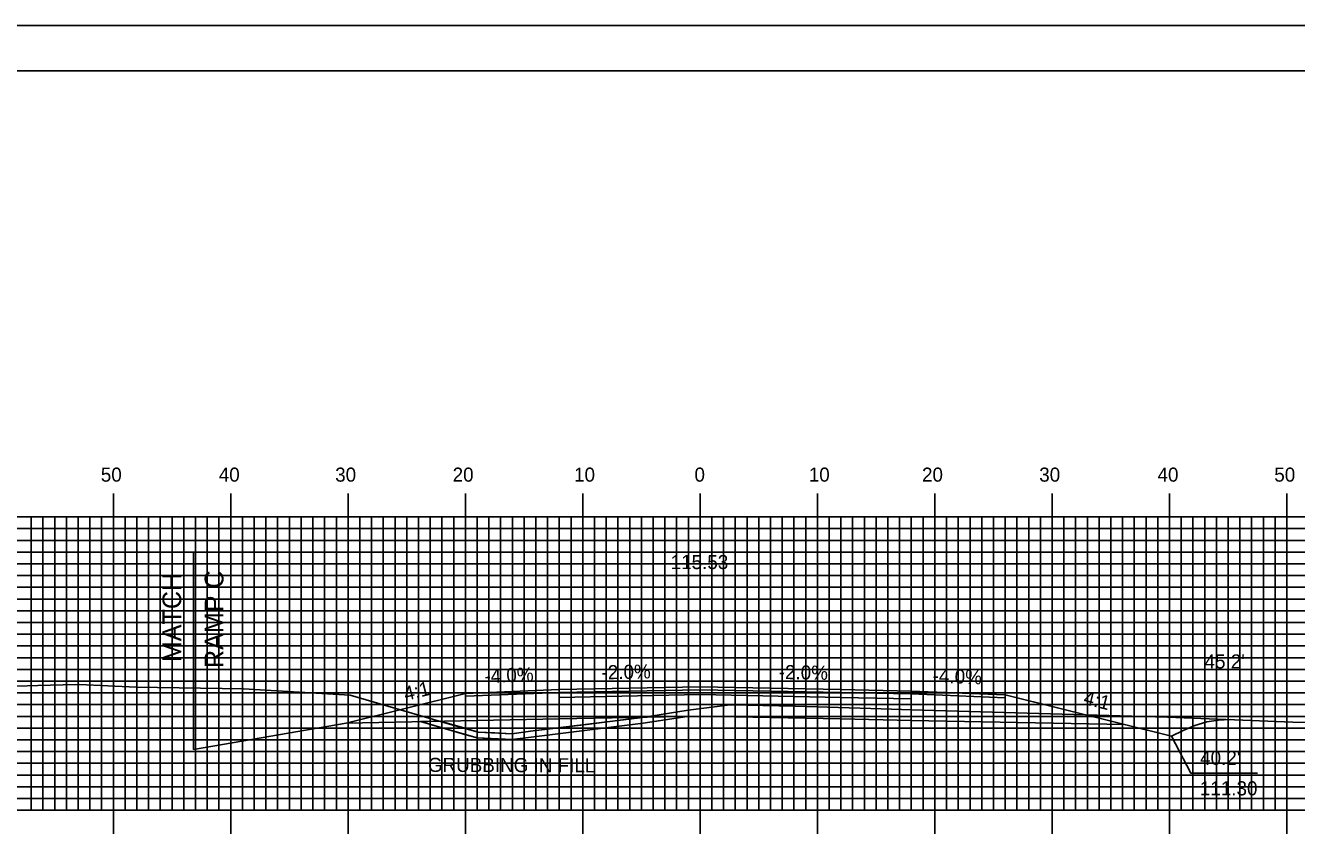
# Model space of a CAD drawing. Extents: x 1754314 to 1754654, y 442591 to 442811.
# Drawn here: x 1754422.5 to 1754530.8, y 442741.2 to 442810.5 of the extents above; entities that cross this region are included whole.
import ezdxf

# ---------------------------------------------------------------- set-up
doc = ezdxf.new("R2010")
doc.units = 0
for name, color, linetype in [('ANNOTATION', 7, 'Continuous'), ('BORDER', 7, 'Continuous'), ('D_Roadway_Centerline', 7, 'Continuous'), ('D_Roadway_Centerline_Text', 7, 'Continuous'), ('D_Roadway_Edge_Shoulder', 7, 'Continuous'), ('D_Roadway_Edge_TW', 7, 'Continuous'), ('D_Roadway_Pavement', 7, 'Continuous'), ('D_Roadway_SlopeLines', 7, 'Continuous'), ('D_Roadway_SubGrade', 7, 'Continuous'), ('D_Text_Standard', 7, 'Continuous'), ('GRUBBING IN FILL', 7, 'Continuous'), ('H_V ANNOTATION', 7, 'Continuous'), ('M_Roadway_Centerline', 7, 'Continuous'), ('MAJOR', 7, 'Continuous'), ('MINOR', 7, 'Continuous'), ('PLOT BOUNDARY', 7, 'Continuous'), ('S_Roadway_Centerline', 7, 'Continuous')]:
    doc.layers.add(name, color=color, linetype=linetype)

msp = doc.modelspace()

# ---------------------------------------------------------------- linework, layer by layer
at = {"layer": 'ANNOTATION'}
msp.add_lwpolyline([(1754527.51, 442746.82), (1754521.82, 442746.82), (1754520.18, 442749.97)], dxfattribs=at)
at = {"layer": 'BORDER'}
msp.add_lwpolyline([(1754330.4, 442596.67), (1754650.4, 442596.67), (1754650.4, 442806.67), (1754330.4, 442806.67)], close=True, dxfattribs=at)
at = {"layer": 'D_Roadway_Centerline'}
msp.add_lwpolyline([(1754436.83, 442748.85), (1754449.83, 442751.09), (1754460, 442753.63), (1754468, 442753.95), (1754480, 442754.19), (1754492, 442753.95), (1754498, 442753.83), (1754506, 442753.51), (1754516.18, 442750.97), (1754520.18, 442749.97), (1754521.17, 442750.46), (1754522.17, 442750.9), (1754523.17, 442751.2), (1754524.17, 442751.36), (1754525.17, 442751.39)], dxfattribs=at)
at = {"layer": 'D_Roadway_Edge_Shoulder'}
for points in [[(1754468, 442753.95), (1754460, 442753.63), (1754460, 442753.38), (1754468, 442753.7)], [(1754498, 442753.83), (1754506, 442753.51), (1754506, 442753.26), (1754498, 442753.58)]]:
    msp.add_lwpolyline(points, close=True, dxfattribs=at)
at = {"layer": 'D_Roadway_Edge_TW'}
for points in [[(1754468, 442753.7), (1754468, 442753.95), (1754480, 442754.19), (1754492, 442753.95), (1754492, 442753.7), (1754480, 442753.94)], [(1754492, 442753.95), (1754498, 442753.83), (1754498, 442753.58), (1754492, 442753.7)]]:
    msp.add_lwpolyline(points, close=True, dxfattribs=at)
at = {"layer": 'D_Roadway_Pavement'}
for points in [[(1754468, 442753.29), (1754468, 442753.7), (1754480, 442753.94), (1754492, 442753.7), (1754492, 442753.29), (1754480, 442753.53)], [(1754492, 442753.7), (1754498, 442753.58), (1754498, 442753.17), (1754492, 442753.29)]]:
    msp.add_lwpolyline(points, close=True, dxfattribs=at)
msp.add_lwpolyline([(1754498, 442753.58), (1754498, 442753.17)], dxfattribs=at)
msp.add_lwpolyline([(1754498, 442753.58), (1754498, 442753.17)], dxfattribs=at)
msp.add_lwpolyline([(1754498, 442753.58), (1754498, 442753.17)], dxfattribs=at)
at = {"layer": 'D_Roadway_SlopeLines'}
for p, q in [((1754460, 442753.63), (1754449.83, 442751.09)), ((1754436.83, 442748.85), (1754436.83, 442753.15)), ((1754449.83, 442751.09), (1754436.83, 442748.85))]:
    msp.add_line(p, q, dxfattribs=at)
for points in [[(1754506, 442753.51), (1754520.18, 442749.97)], [(1754520.18, 442749.97), (1754521.17, 442750.46), (1754522.17, 442750.9), (1754523.17, 442751.2), (1754524.17, 442751.36), (1754525.17, 442751.39)]]:
    msp.add_lwpolyline(points, dxfattribs=at)
at = {"layer": 'D_Roadway_SubGrade'}
msp.add_line((1754436.83, 442765.63), (1754436.83, 442748.85), dxfattribs=at)
for points in [[(1754460, 442753.38), (1754468, 442753.7), (1754468, 442753.29), (1754468, 442751.45), (1754449.83, 442751.09), (1754460, 442753.63)], [(1754468, 442751.45), (1754468, 442753.29), (1754480, 442753.53), (1754492, 442753.29), (1754492, 442751.45), (1754480, 442751.69)], [(1754498, 442753.17), (1754498, 442753.58), (1754506, 442753.26), (1754506, 442753.51), (1754516.18, 442750.97), (1754498, 442751.33)], [(1754492, 442753.29), (1754498, 442753.17), (1754498, 442751.33), (1754492, 442751.45)]]:
    msp.add_lwpolyline(points, close=True, dxfattribs=at)
at = {"layer": 'GRUBBING IN FILL'}
msp.add_lwpolyline([(1754456.18, 442751.22), (1754458.5, 442750.54), (1754461, 442749.83), (1754463.98, 442749.69), (1754465.61, 442749.9), (1754475.15, 442751.09), (1754478.9, 442751.67)], dxfattribs=at)
msp.add_lwpolyline([(1754456.18, 442751.22), (1754458.5, 442750.54), (1754461, 442749.83), (1754463.98, 442749.69), (1754465.61, 442749.9), (1754475.15, 442751.09), (1754478.9, 442751.67)], dxfattribs=at)
msp.add_lwpolyline([(1754456.18, 442751.22), (1754457.86, 442751.25), (1754459.86, 442750.68), (1754461.08, 442750.33), (1754462.52, 442750.26), (1754463.96, 442750.19), (1754464.75, 442750.29), (1754465.54, 442750.4), (1754470.31, 442750.99), (1754475.18, 442751.6), (1754478.9, 442751.67), (1754475.15, 442751.09), (1754470.38, 442750.49), (1754465.61, 442749.9), (1754463.98, 442749.69), (1754462.49, 442749.76), (1754461, 442749.83), (1754459.75, 442750.19)], close=True, dxfattribs=at)
msp.add_lwpolyline([(1754456.18, 442751.22), (1754457.86, 442751.25), (1754459.86, 442750.68), (1754461.08, 442750.33), (1754462.52, 442750.26), (1754463.96, 442750.19), (1754464.75, 442750.29), (1754465.54, 442750.4), (1754470.31, 442750.99), (1754475.18, 442751.6), (1754478.9, 442751.67), (1754475.15, 442751.09), (1754470.38, 442750.49), (1754465.61, 442749.9), (1754463.98, 442749.69), (1754462.49, 442749.76), (1754461, 442749.83), (1754459.75, 442750.19)], close=True, dxfattribs=at)
at = {"layer": 'MAJOR'}
for p, q in [((1754430, 442770.67), (1754430, 442768.67)), ((1754440, 442770.67), (1754440, 442768.67)), ((1754450, 442770.67), (1754450, 442768.67)), ((1754460, 442770.67), (1754460, 442768.67)), ((1754470, 442770.67), (1754470, 442768.67)), ((1754480, 442770.67), (1754480, 442768.67)), ((1754490, 442770.67), (1754490, 442768.67)), ((1754500, 442770.67), (1754500, 442768.67)), ((1754510, 442770.67), (1754510, 442768.67)), ((1754520, 442770.67), (1754520, 442768.67)), ((1754530, 442770.67), (1754530, 442768.67)), ((1754340, 442768.67), (1754620, 442768.67)), ((1754340, 442768.67), (1754620, 442768.67)), ((1754430, 442743.67), (1754430, 442768.67)), ((1754440, 442743.67), (1754440, 442768.67)), ((1754450, 442743.67), (1754450, 442768.67)), ((1754460, 442743.67), (1754460, 442768.67)), ((1754470, 442743.67), (1754470, 442768.67)), ((1754480, 442743.67), (1754480, 442768.67)), ((1754490, 442743.67), (1754490, 442768.67)), ((1754500, 442743.67), (1754500, 442768.67)), ((1754510, 442743.67), (1754510, 442768.67)), ((1754520, 442743.67), (1754520, 442768.67)), ((1754530, 442743.67), (1754530, 442768.67)), ((1754340, 442763.67), (1754620, 442763.67)), ((1754340, 442758.67), (1754620, 442758.67)), ((1754340, 442753.67), (1754620, 442753.67)), ((1754340, 442748.67), (1754620, 442748.67)), ((1754340, 442743.67), (1754620, 442743.67)), ((1754340, 442743.67), (1754620, 442743.67)), ((1754430, 442741.66), (1754430, 442743.67)), ((1754440, 442741.66), (1754440, 442743.67)), ((1754450, 442741.66), (1754450, 442743.67)), ((1754460, 442741.66), (1754460, 442743.67)), ((1754470, 442741.66), (1754470, 442743.67)), ((1754480, 442741.66), (1754480, 442743.67)), ((1754490, 442741.66), (1754490, 442743.67)), ((1754500, 442741.66), (1754500, 442743.67)), ((1754510, 442741.66), (1754510, 442743.67)), ((1754520, 442741.66), (1754520, 442743.67)), ((1754530, 442741.66), (1754530, 442743.67))]:
    msp.add_line(p, q, dxfattribs=at)
at = {"layer": 'MINOR'}
for p, q in [((1754423, 442743.67), (1754423, 442768.67)), ((1754424, 442743.67), (1754424, 442768.67)), ((1754425, 442743.67), (1754425, 442768.67)), ((1754426, 442743.67), (1754426, 442768.67)), ((1754427, 442743.67), (1754427, 442768.67)), ((1754428, 442743.67), (1754428, 442768.67)), ((1754429, 442743.67), (1754429, 442768.67)), ((1754431, 442743.67), (1754431, 442768.67)), ((1754432, 442743.67), (1754432, 442768.67)), ((1754433, 442743.67), (1754433, 442768.67)), ((1754434, 442743.67), (1754434, 442768.67)), ((1754435, 442743.67), (1754435, 442768.67)), ((1754436, 442743.67), (1754436, 442768.67)), ((1754437, 442743.67), (1754437, 442768.67)), ((1754438, 442743.67), (1754438, 442768.67)), ((1754439, 442743.67), (1754439, 442768.67)), ((1754441, 442743.67), (1754441, 442768.67)), ((1754442, 442743.67), (1754442, 442768.67)), ((1754443, 442743.67), (1754443, 442768.67)), ((1754444, 442743.67), (1754444, 442768.67)), ((1754445, 442743.67), (1754445, 442768.67)), ((1754446, 442743.67), (1754446, 442768.67)), ((1754447, 442743.67), (1754447, 442768.67)), ((1754448, 442743.67), (1754448, 442768.67)), ((1754449, 442743.67), (1754449, 442768.67)), ((1754451, 442743.67), (1754451, 442768.67)), ((1754452, 442743.67), (1754452, 442768.67)), ((1754453, 442743.67), (1754453, 442768.67)), ((1754454, 442743.67), (1754454, 442768.67)), ((1754455, 442743.67), (1754455, 442768.67)), ((1754456, 442743.67), (1754456, 442768.67)), ((1754457, 442743.67), (1754457, 442768.67)), ((1754458, 442743.67), (1754458, 442768.67)), ((1754459, 442743.67), (1754459, 442768.67)), ((1754461, 442743.67), (1754461, 442768.67)), ((1754462, 442743.67), (1754462, 442768.67)), ((1754463, 442743.67), (1754463, 442768.67)), ((1754464, 442743.67), (1754464, 442768.67)), ((1754465, 442743.67), (1754465, 442768.67)), ((1754466, 442743.67), (1754466, 442768.67)), ((1754467, 442743.67), (1754467, 442768.67)), ((1754468, 442743.67), (1754468, 442768.67)), ((1754469, 442743.67), (1754469, 442768.67)), ((1754471, 442743.67), (1754471, 442768.67)), ((1754472, 442743.67), (1754472, 442768.67)), ((1754473, 442743.67), (1754473, 442768.67)), ((1754474, 442743.67), (1754474, 442768.67)), ((1754475, 442743.67), (1754475, 442768.67)), ((1754476, 442743.67), (1754476, 442768.67)), ((1754477, 442743.67), (1754477, 442768.67)), ((1754478, 442743.67), (1754478, 442768.67)), ((1754479, 442743.67), (1754479, 442768.67)), ((1754481, 442743.67), (1754481, 442768.67)), ((1754482, 442743.67), (1754482, 442768.67)), ((1754483, 442743.67), (1754483, 442768.67)), ((1754484, 442743.67), (1754484, 442768.67)), ((1754485, 442743.67), (1754485, 442768.67)), ((1754486, 442743.67), (1754486, 442768.67)), ((1754487, 442743.67), (1754487, 442768.67)), ((1754488, 442743.67), (1754488, 442768.67)), ((1754489, 442743.67), (1754489, 442768.67)), ((1754491, 442743.67), (1754491, 442768.67)), ((1754492, 442743.67), (1754492, 442768.67)), ((1754493, 442743.67), (1754493, 442768.67)), ((1754494, 442743.67), (1754494, 442768.67)), ((1754495, 442743.67), (1754495, 442768.67)), ((1754496, 442743.67), (1754496, 442768.67)), ((1754497, 442743.67), (1754497, 442768.67)), ((1754498, 442743.67), (1754498, 442768.67)), ((1754499, 442743.67), (1754499, 442768.67)), ((1754501, 442743.67), (1754501, 442768.67)), ((1754502, 442743.67), (1754502, 442768.67)), ((1754503, 442743.67), (1754503, 442768.67)), ((1754504, 442743.67), (1754504, 442768.67)), ((1754505, 442743.67), (1754505, 442768.67)), ((1754506, 442743.67), (1754506, 442768.67)), ((1754507, 442743.67), (1754507, 442768.67)), ((1754508, 442743.67), (1754508, 442768.67)), ((1754509, 442743.67), (1754509, 442768.67)), ((1754511, 442743.67), (1754511, 442768.67)), ((1754512, 442743.67), (1754512, 442768.67)), ((1754513, 442743.67), (1754513, 442768.67)), ((1754514, 442743.67), (1754514, 442768.67)), ((1754515, 442743.67), (1754515, 442768.67)), ((1754516, 442743.67), (1754516, 442768.67)), ((1754517, 442743.67), (1754517, 442768.67)), ((1754518, 442743.67), (1754518, 442768.67)), ((1754519, 442743.67), (1754519, 442768.67)), ((1754521, 442743.67), (1754521, 442768.67)), ((1754522, 442743.67), (1754522, 442768.67)), ((1754523, 442743.67), (1754523, 442768.67)), ((1754524, 442743.67), (1754524, 442768.67)), ((1754525, 442743.67), (1754525, 442768.67)), ((1754526, 442743.67), (1754526, 442768.67)), ((1754527, 442743.67), (1754527, 442768.67)), ((1754528, 442743.67), (1754528, 442768.67)), ((1754529, 442743.67), (1754529, 442768.67)), ((1754340, 442767.67), (1754620, 442767.67)), ((1754340, 442766.67), (1754620, 442766.67)), ((1754340, 442765.67), (1754620, 442765.67)), ((1754340, 442764.67), (1754620, 442764.67)), ((1754340, 442762.67), (1754620, 442762.67)), ((1754340, 442761.67), (1754620, 442761.67)), ((1754340, 442760.67), (1754620, 442760.67)), ((1754340, 442759.67), (1754620, 442759.67)), ((1754340, 442757.67), (1754620, 442757.67)), ((1754340, 442756.67), (1754620, 442756.67)), ((1754340, 442755.67), (1754620, 442755.67)), ((1754340, 442754.67), (1754620, 442754.67)), ((1754340, 442752.67), (1754620, 442752.67)), ((1754340, 442751.67), (1754620, 442751.67)), ((1754340, 442750.67), (1754620, 442750.67)), ((1754340, 442749.67), (1754620, 442749.67)), ((1754340, 442747.67), (1754620, 442747.67)), ((1754340, 442746.67), (1754620, 442746.67)), ((1754340, 442745.67), (1754620, 442745.67)), ((1754340, 442744.67), (1754620, 442744.67))]:
    msp.add_line(p, q, dxfattribs=at)
at = {"layer": 'PLOT BOUNDARY'}
msp.add_lwpolyline([(1754314.22, 442590.55), (1754654.22, 442590.55), (1754654.22, 442810.55), (1754314.22, 442810.55)], close=True, dxfattribs=at)
at = {"layer": 'S_Roadway_Centerline'}
msp.add_lwpolyline([(1754421.76, 442754.24), (1754423.56, 442754.3), (1754425.72, 442754.37), (1754427.1, 442754.39), (1754431.93, 442754.17), (1754441.08, 442754.02), (1754445.36, 442753.77), (1754450.17, 442753.48), (1754458.64, 442751.02), (1754461.08, 442750.33), (1754463.96, 442750.19), (1754465.54, 442750.4), (1754475.08, 442751.58), (1754478.98, 442752.19), (1754482.57, 442752.66), (1754488.09, 442752.53), (1754494.56, 442752.34), (1754498.91, 442752.2), (1754514.83, 442751.74), (1754517.77, 442751.67), (1754519.83, 442751.59), (1754530.52, 442751.19), (1754536.97, 442751.01)], dxfattribs=at)

# ---------------------------------------------------------------- texts
at = {"layer": 'ANNOTATION'}
for s, height, rotation, p in [('MATCH', 1.6, 90, (1754435.78, 442756.29)), ('RAMP C', 1.6, 90, (1754439.38, 442755.79)), ('-4.0%', 1.2, 2.2906, (1754461.64, 442754.5)), ('-2.0%', 1.2, 1.1458, (1754471.61, 442754.82)), ('-2.0%', 1.2, 358.8542, (1754486.69, 442754.86)), ('-4.0%', 1.2, 357.7094, (1754499.8, 442754.56)), ('4:1', 1.2, 14.0381, (1754454.91, 442752.98)), ('4:1', 1.2, 345.9638, (1754512.6, 442752.73))]:
    msp.add_text(s, height=height, rotation=rotation, dxfattribs=at).set_placement(p)
for s, p in [("40.2'", (1754522.61, 442747.54)), ('111.30', (1754522.59, 442744.94))]:
    msp.add_text(s, height=1.2, dxfattribs=at).set_placement(p)
at = {"layer": 'D_Roadway_Centerline'}
for s, p in [('C', (1754480, 442754.19)), ('L', (1754480, 442754.18))]:
    msp.add_text(s, height=0.0146, dxfattribs=at).set_placement(p)
at = {"layer": 'D_Roadway_Centerline_Text'}
msp.add_text('115.53', height=1.2, dxfattribs=at).set_placement((1754477.49, 442764.22))
at = {"layer": 'D_Text_Standard'}
msp.add_text("45.2'", height=1.2, dxfattribs=at).set_placement((1754522.99, 442755.75))
at = {"layer": 'GRUBBING IN FILL'}
msp.add_text('GRUBBING IN FILL', height=1.2, rotation=359.8142, dxfattribs=at).set_placement((1754456.8, 442746.94))
at = {"layer": 'H_V ANNOTATION'}
for s, p in [('50', (1754428.93, 442771.67)), ('40', (1754438.98, 442771.67)), ('30', (1754448.9, 442771.67)), ('20', (1754458.91, 442771.67)), ('10', (1754469.26, 442771.67)), ('0', (1754479.52, 442771.67)), ('10', (1754489.26, 442771.67)), ('20', (1754498.91, 442771.67)), ('30', (1754508.9, 442771.67)), ('40', (1754518.98, 442771.67)), ('50', (1754528.93, 442771.67))]:
    msp.add_text(s, height=1.2, dxfattribs=at).set_placement(p)
at = {"layer": 'M_Roadway_Centerline'}
for s, p in [('C', (1754425.72, 442754.37)), ('L', (1754425.71, 442754.36))]:
    msp.add_text(s, height=0.0146, dxfattribs=at).set_placement(p)

doc.saveas('drawing.dxf')
